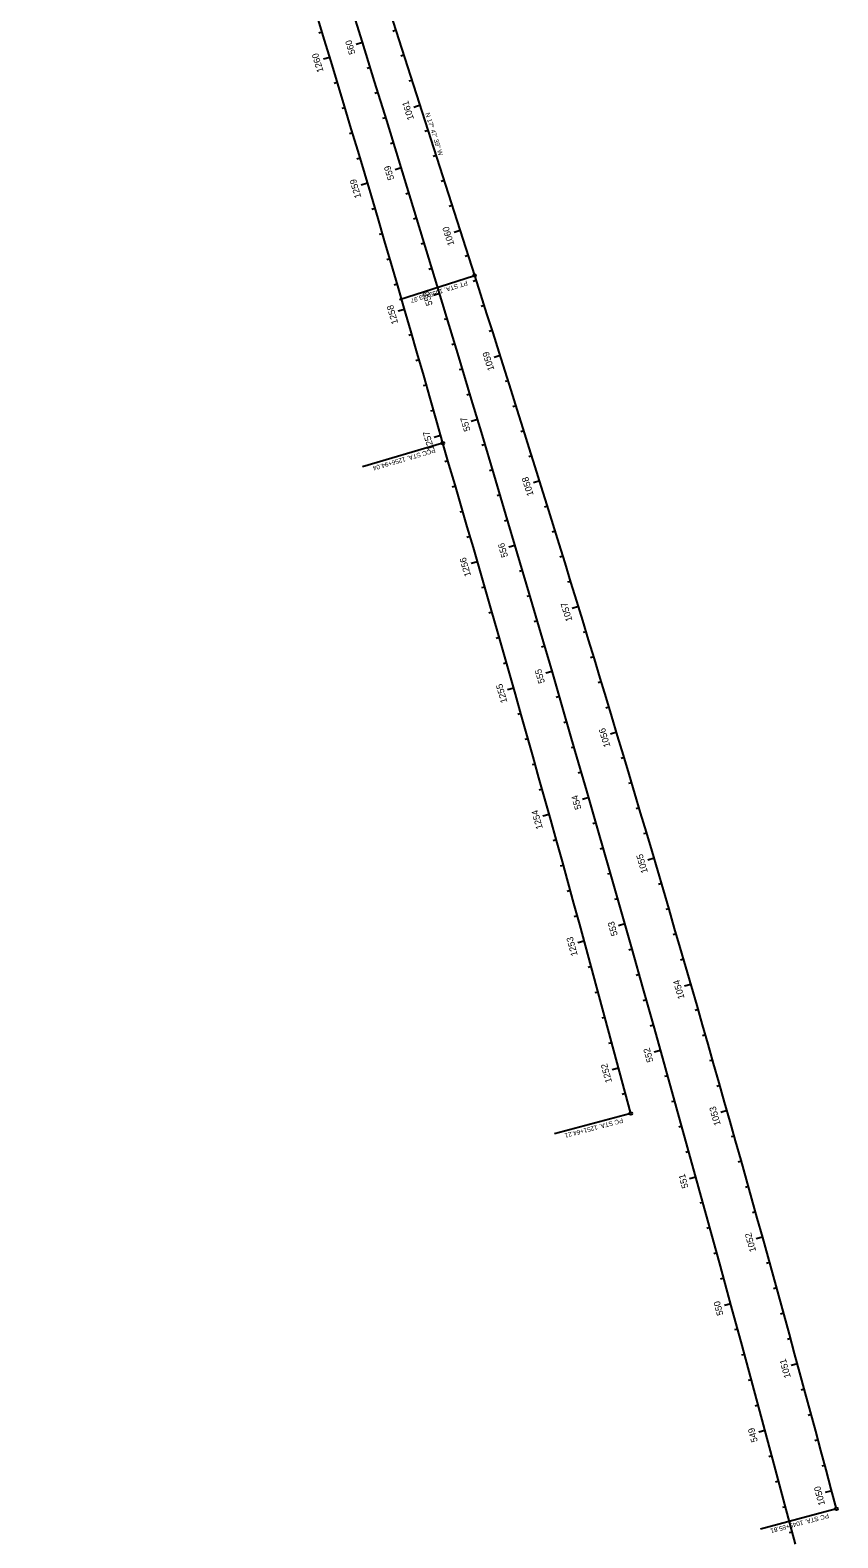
# Model space of a CAD drawing. Extents: x 919452 to 931278, y 583254 to 665650.
# Drawn here: x 929643 to 930257, y 630843 to 631990 of the extents above; entities that cross this region are included whole.
import ezdxf

# ---------------------------------------------------------------- set-up
doc = ezdxf.new("R2010")
doc.units = 0
for name, color, linetype in [('CLConst_dp', 7, 'Continuous'), ('CurveDataLabel_dp', 7, 'Continuous'), ('StationTicL_dp', 7, 'Continuous'), ('StationTicS_dp', 7, 'Continuous'), ('TextBLStation', 7, 'Continuous'), ('TextLabel', 7, 'Continuous')]:
    doc.layers.add(name, color=color, linetype=linetype)

msp = doc.modelspace()

# ---------------------------------------------------------------- linework, layer by layer
at = {"layer": 'CLConst_dp'}
msp.add_line((929981.1, 631803.6), (929914.7, 632010.7), dxfattribs=at)
for centre, radius, start, end in [((902539.3, 623476.4), 28647.9, 14.89045, 18.89818), ((915541.2, 627610.5), 14978, 15.74941, 17.92872), ((911604.4, 625905.5), 19300, 14.89045, 17.7943), ((910794.6, 626032.5), 19976, 14.89045, 16.41013)]:
    msp.add_arc(centre, radius, start, end, dxfattribs=at)
at = {"layer": 'CurveDataLabel_dp'}
for p, q in [((929980.2, 631803.2), (929923.8, 631785.1)), ((929955.9, 631675.7), (929895.8, 631658)), ((930098.8, 631165.5), (930041.9, 631150.4)), ((930255.4, 630864.8), (930198.5, 630849.6))]:
    msp.add_line(p, q, dxfattribs=at)
for centre in [(929981.1, 631803.6), (929956.9, 631676), (930099.8, 631165.8), (930256.3, 630865)]:
    msp.add_circle(centre, 1, dxfattribs=at)
at = {"layer": 'StationTicL_dp'}
for p, q in [((929895.7, 631981), (929891, 631979.5)), ((929870.8, 631969.6), (929866, 631968.1)), ((929939.6, 631933.1), (929934.8, 631931.5)), ((929925.3, 631885.5), (929920.5, 631884)), ((929899.6, 631873.8), (929894.8, 631872.4)), ((929970.1, 631837.9), (929965.4, 631836.3)), ((929954.5, 631789.8), (929949.7, 631788.4)), ((929927.7, 631777.8), (929922.9, 631776.4)), ((930000.6, 631742.6), (929995.8, 631741.1)), ((929983.3, 631694.1), (929978.5, 631692.6)), ((929955.2, 631681.7), (929950.4, 631680.3)), ((930030.6, 631647.2), (930025.8, 631645.7)), ((930011.8, 631598.2), (930007, 631596.8)), ((929983.2, 631585.7), (929978.4, 631584.3)), ((930060.1, 631551.7), (930055.3, 631550.2)), ((930040, 631502.3), (930035.2, 631500.9)), ((930010.8, 631489.6), (930006, 631488.2)), ((930089.1, 631456), (930084.3, 631454.5)), ((930067.9, 631406.2), (930063.1, 631404.8)), ((930037.8, 631393.3), (930033, 631392)), ((930117.6, 631360.1), (930112.8, 631358.7)), ((930095.4, 631310.1), (930090.6, 631308.7)), ((930064.4, 631296.9), (930059.6, 631295.6)), ((930145.6, 631264.1), (930140.8, 631262.7)), ((930122.5, 631213.9), (930117.7, 631212.5)), ((930090.6, 631200.4), (930085.7, 631199.1)), ((930173.1, 631168), (930168.3, 631166.6)), ((930149.4, 631117.5), (930144.6, 631116.2)), ((930200.1, 631071.7), (930195.3, 631070.4)), ((930175.9, 631021.1), (930171.1, 631019.8)), ((930226.7, 630975.3), (930221.8, 630974)), ((930202.1, 630924.6), (930197.2, 630923.3)), ((930252.7, 630878.7), (930247.8, 630877.4))]:
    msp.add_line(p, q, dxfattribs=at)
at = {"layer": 'StationTicS_dp'}
for p, q in [((929921.2, 631990.2), (929918.8, 631989.4)), ((929865, 631988.7), (929862.6, 631988)), ((929927.3, 631971.2), (929925, 631970.4)), ((929901.7, 631961.9), (929899.3, 631961.2)), ((929876.6, 631950.4), (929874.2, 631949.7)), ((929933.4, 631952.1), (929931.1, 631951.4)), ((929907.6, 631942.8), (929905.2, 631942.1)), ((929882.4, 631931.3), (929880, 631930.6)), ((929913.5, 631923.7), (929911.1, 631923)), ((929888.2, 631912.1), (929885.8, 631911.4)), ((929945.7, 631914), (929943.3, 631913.3)), ((929919.4, 631904.6), (929917, 631903.8)), ((929893.9, 631893), (929891.5, 631892.2)), ((929951.8, 631895), (929949.4, 631894.2)), ((929957.9, 631875.9), (929955.5, 631875.2)), ((929931.1, 631866.3), (929928.7, 631865.6)), ((929905.3, 631854.6), (929902.9, 631853.9)), ((929964, 631856.9), (929961.6, 631856.1)), ((929937, 631847.2), (929934.6, 631846.5)), ((929910.9, 631835.4), (929908.5, 631834.7)), ((929942.8, 631828.1), (929940.4, 631827.4)), ((929976.2, 631818.8), (929973.8, 631818.1)), ((929916.6, 631816.2), (929914.2, 631815.5)), ((929948.6, 631809), (929946.3, 631808.2)), ((929922.2, 631797), (929919.8, 631796.3)), ((929982.3, 631799.8), (929980, 631799)), ((929988.4, 631780.7), (929986.1, 631780)), ((929960.3, 631770.7), (929957.9, 631770)), ((929994.5, 631761.7), (929992.1, 631760.9)), ((929933.3, 631758.6), (929930.9, 631757.9)), ((929966, 631751.5), (929963.6, 631750.8)), ((929938.8, 631739.4), (929936.4, 631738.7)), ((929971.8, 631732.4), (929969.4, 631731.7)), ((929944.3, 631720.2), (929941.9, 631719.5)), ((930006.6, 631723.5), (930004.2, 631722.8)), ((929977.6, 631713.2), (929975.2, 631712.5)), ((930012.6, 631704.5), (930010.2, 631703.7)), ((929949.8, 631700.9), (929947.4, 631700.3)), ((930018.6, 631685.4), (930016.2, 631684.6)), ((929989, 631674.9), (929986.6, 631674.2)), ((929960.8, 631662.5), (929958.4, 631661.8)), ((930024.6, 631666.3), (930022.2, 631665.6)), ((929994.8, 631655.7), (929992.4, 631655)), ((929966.4, 631643.3), (929964, 631642.6)), ((930000.5, 631636.6), (929998.1, 631635.9)), ((929972.1, 631624.1), (929969.7, 631623.4)), ((930036.5, 631628.1), (930034.1, 631627.4)), ((930006.1, 631617.4), (930003.8, 631616.7)), ((929977.6, 631604.9), (929975.2, 631604.2)), ((930042.4, 631609), (930040, 631608.3)), ((930048.3, 631589.9), (930045.9, 631589.2)), ((930017.5, 631579), (930015.1, 631578.3)), ((929988.8, 631566.5), (929986.4, 631565.8)), ((930054.2, 631570.8), (930051.8, 631570.1)), ((930023.1, 631559.9), (930020.7, 631559.2)), ((929994.3, 631547.3), (929991.9, 631546.6)), ((930028.8, 631540.7), (930026.4, 631540)), ((930065.9, 631532.5), (930063.5, 631531.8)), ((929999.8, 631528), (929997.4, 631527.3)), ((930034.4, 631521.5), (930032, 631520.8)), ((930005.3, 631508.8), (930002.9, 631508.1)), ((930071.7, 631513.4), (930069.3, 631512.7)), ((930077.5, 631494.3), (930075.1, 631493.5)), ((930045.6, 631483.1), (930043.2, 631482.4)), ((930083.3, 631475.1), (930080.9, 631474.4)), ((930016.2, 631470.3), (930013.8, 631469.6)), ((930051.2, 631463.9), (930048.8, 631463.2)), ((930021.7, 631451.1), (930019.3, 631450.4)), ((930056.8, 631444.7), (930054.4, 631444)), ((930027.1, 631431.8), (930024.7, 631431.1)), ((930094.8, 631436.8), (930092.4, 631436.1)), ((930062.3, 631425.5), (930059.9, 631424.8)), ((930100.5, 631417.6), (930098.1, 631416.9)), ((930032.5, 631412.6), (930030.1, 631411.9)), ((930106.2, 631398.5), (930103.9, 631397.8)), ((930073.4, 631387), (930071, 631386.3)), ((930043.2, 631374), (930040.8, 631373.4)), ((930111.9, 631379.3), (930109.5, 631378.6)), ((930078.9, 631367.8), (930076.5, 631367.1)), ((930048.5, 631354.7), (930046.1, 631354.1)), ((930084.4, 631348.6), (930082, 631347.9)), ((930053.9, 631335.5), (930051.5, 631334.8)), ((930123.2, 631340.9), (930120.8, 631340.2)), ((930089.9, 631329.3), (930087.5, 631328.6)), ((930059.2, 631316.2), (930056.8, 631315.5)), ((930128.9, 631321.7), (930126.5, 631321)), ((930134.5, 631302.5), (930132.1, 631301.8)), ((930100.8, 631290.9), (930098.4, 631290.2)), ((930069.7, 631277.6), (930067.3, 631276.9)), ((930140, 631283.3), (930137.6, 631282.6)), ((930106.3, 631271.6), (930103.9, 631270.9)), ((930074.9, 631258.3), (930072.5, 631257.6)), ((930111.7, 631252.4), (930109.3, 631251.7)), ((930151.1, 631244.9), (930148.7, 631244.2)), ((930080.2, 631239), (930077.8, 631238.3)), ((930117.1, 631233.1), (930114.7, 631232.4)), ((930156.7, 631225.7), (930154.3, 631225)), ((930085.4, 631219.7), (930083, 631219)), ((930162.2, 631206.5), (930159.8, 631205.8)), ((930127.9, 631194.6), (930125.5, 631193.9)), ((930167.7, 631187.2), (930165.3, 631186.5)), ((930095.7, 631181), (930093.3, 631180.4)), ((930133.3, 631175.3), (930130.9, 631174.7)), ((930138.7, 631156.1), (930136.3, 631155.4)), ((930178.6, 631148.7), (930176.2, 631148.1)), ((930144, 631136.8), (930141.6, 631136.1)), ((930184, 631129.5), (930181.6, 631128.8)), ((930189.4, 631110.2), (930187, 631109.6)), ((930154.7, 631098.2), (930152.3, 631097.6)), ((930194.8, 631091), (930192.4, 631090.3)), ((930160, 631079), (930157.6, 631078.3)), ((930165.3, 631059.7), (930162.9, 631059)), ((930205.5, 631052.4), (930203.1, 631051.8)), ((930170.6, 631040.4), (930168.2, 631039.7)), ((930210.8, 631033.2), (930208.4, 631032.5)), ((930216.1, 631013.9), (930213.7, 631013.2)), ((930181.2, 631001.8), (930178.7, 631001.1)), ((930221.4, 630994.6), (930219, 630993.9)), ((930186.4, 630982.5), (930184, 630981.9)), ((930191.6, 630963.2), (930189.2, 630962.6)), ((930231.9, 630956), (930229.5, 630955.3)), ((930196.9, 630943.9), (930194.4, 630943.2)), ((930237.1, 630936.7), (930234.7, 630936)), ((930242.3, 630917.4), (930239.9, 630916.7)), ((930207.3, 630905.3), (930204.8, 630904.6)), ((930247.5, 630898), (930245.1, 630897.4)), ((930212.4, 630886), (930210, 630885.3)), ((930217.6, 630866.6), (930215.2, 630866)), ((930222.7, 630847.3), (930220.3, 630846.7))]:
    msp.add_line(p, q, dxfattribs=at)

# ---------------------------------------------------------------- texts
at = {"layer": 'CurveDataLabel_dp'}
for s, rotation, p in [('PT STA. 1059+63.97', 197.7943, (929975, 631799.7)), ('PCC STA. 1256+94.04', 196.4101, (929950.6, 631672.3)), ('PC STA. 1251+64.21', 194.8905, (930093.5, 631162.3)), ('PC STA. 1049+85.81', 194.8905, (930250, 630861.5))]:
    msp.add_text(s, height=3.5, rotation=rotation, dxfattribs=at).set_placement(p)
at = {"layer": 'TextBLStation'}
for s, rotation, p in [('560', 107.2694, (929890.5, 631972.6)), ('1260', 106.9198, (929866.2, 631959)), ('1061', 107.7943, (929935, 631922.8)), ('559', 107.0694, (929920, 631877)), ('1259', 106.5373, (929894.9, 631863.2)), ('1060', 107.7943, (929965.7, 631827.2)), ('558', 106.8694, (929949.2, 631781.4)), ('1258', 106.1547, (929923, 631767.3)), ('1059', 107.6044, (929996.1, 631732)), ('557', 106.6694, (929978, 631685.7)), ('1257', 105.7722, (929950.4, 631671.3)), ('1058', 107.3075, (930026, 631636.6)), ('556', 106.4694, (930006.5, 631589.8)), ('1256', 106.1404, (929978.4, 631575.2)), ('1057', 107.0107, (930055.5, 631541.1)), ('555', 106.2694, (930034.6, 631493.9)), ('1255', 105.8536, (930006, 631479)), ('1056', 106.7138, (930084.4, 631445.4)), ('554', 106.0694, (930062.4, 631397.9)), ('1254', 105.5668, (930033, 631382.9)), ('1055', 106.4169, (930112.9, 631349.5)), ('553', 105.8694, (930090, 631301.7)), ('1253', 105.2799, (930059.5, 631286.4)), ('1054', 106.1201, (930140.8, 631253.7)), ('552', 105.6694, (930117.1, 631205.5)), ('1252', 104.9931, (930085.6, 631189.9)), ('1053', 105.8232, (930168.3, 631157.4)), ('551', 105.4694, (930143.8, 631109.6)), ('1052', 105.5263, (930195.3, 631061.2)), ('550', 105.2694, (930170.4, 631012.8)), ('1051', 105.2294, (930221.6, 630965.2)), ('549', 105.0694, (930196.5, 630916.3)), ('1050', 104.9326, (930247.7, 630868.3))]:
    msp.add_text(s, height=5, rotation=rotation, dxfattribs=at).set_placement(p)
at = {"layer": 'TextLabel'}
msp.add_text('N 17%%d 47\' 39" W', height=3.5, rotation=287.7943, dxfattribs=at).set_placement((929943.4, 631926.9))

doc.saveas('drawing.dxf')
